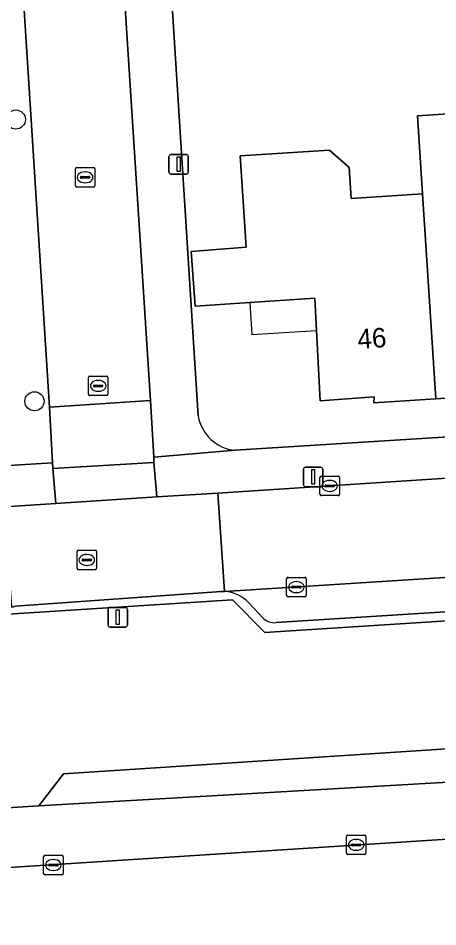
# Model space of a CAD drawing. Extents: x 159626 to 160723, y 388173 to 389416.
# Drawn here: x 160440.24 to 160461.73, y 388327.53 to 388374.02 of the extents above; entities that cross this region are included whole.
import ezdxf

# ---------------------------------------------------------------- set-up
doc = ezdxf.new("R2010")
doc.units = 0
for name, color, linetype in [('IMGEO_Boom', 7, 'Continuous'), ('IMGEO_Erf', 7, 'Continuous'), ('IMGEO_Groenvoorziening', 7, 'Continuous'), ('IMGEO_Kolk', 7, 'Continuous'), ('IMGEO_Lichtmast', 7, 'Continuous'), ('IMGEO_Pand', 7, 'Continuous'), ('IMGEO_Pand_nummerreeks', 7, 'Continuous'), ('IMGEO_Pand_overbouw', 7, 'Continuous'), ('IMGEO_Parkeervlak_open', 7, 'Continuous'), ('IMGEO_Rijbaan_lokaal_open', 7, 'Continuous'), ('IMGEO_Rijbaan_regionaal_gesloten', 7, 'Continuous'), ('IMGEO_Rioolput', 7, 'Continuous'), ('IMGEO_Verkeersbordpaal', 7, 'Continuous'), ('IMGEO_Voetpad_open', 7, 'Continuous')]:
    doc.layers.add(name, color=color, linetype=linetype)

msp = doc.modelspace()

# ---------------------------------------------------------------- linework, layer by layer
at = {"layer": 'IMGEO_Boom'}
for centre in [(160440.123, 388368.835), (160441.073, 388354.42)]:
    msp.add_circle(centre, 0.489, dxfattribs=at)
at = {"layer": 'IMGEO_Erf'}
for points in [[(160505.042, 388420.291), (160500, 388419.981), (160493.644, 388419.591), (160475.279, 388418.463), (160445.47, 388416.632), (160449.463, 388353.672)], [(160464.685, 388354.744), (160461.629, 388354.549), (160458.458, 388354.346), (160458.462, 388354.644), (160455.697, 388354.445), (160455.515, 388358.041), (160455.431, 388359.702), (160452.096, 388359.469), (160449.31, 388359.292), (160449.094, 388362.083), (160451.908, 388362.301), (160451.598, 388366.977), (160456.188, 388367.277), (160457.179, 388366.384), (160457.282, 388364.797), (160460.949, 388365.037), (160460.69, 388369.028), (160469.61, 388369.607)], [(160451.349, 388351.913), (160500, 388354.96), (160500.784, 388355.009), (160506.512, 388355.368)]]:
    msp.add_lwpolyline(points, dxfattribs=at)
msp.add_arc((160451.536, 388354.004), 2.1, 189.1106, 264.8804, dxfattribs=at)
at = {"layer": 'IMGEO_Groenvoorziening'}
for points in [[(160398.695, 388331.202), (160403.057, 388331.467), (160403.067, 388331.305), (160441.302, 388333.713), (160442.552, 388335.356), (160467.15, 388336.963), (160467.275, 388335.225), (160501.835, 388337.484), (160501.213, 388347.873), (160500, 388347.802), (160491.895, 388347.305), (160490.539, 388345.566), (160490.061, 388345.143)], [(160489.377, 388344.926), (160452.877, 388342.587), (160451.214, 388344.256), (160439.719, 388343.519), (160437.971, 388341.554), (160397.13, 388338.982), (160397.594, 388332.119)], [(160501.982, 388335.024), (160501.835, 388337.484), (160467.275, 388335.225), (160441.302, 388333.713), (160403.067, 388331.305), (160403.258, 388328.243), (160416.129, 388329.131), (160431.58, 388330.029), (160482.533, 388333.323), (160501.552, 388334.526)]]:
    msp.add_lwpolyline(points, dxfattribs=at)
msp.add_lwpolyline([(160467.275, 388335.225), (160467.15, 388336.963), (160442.552, 388335.356), (160441.302, 388333.713)], close=True, dxfattribs=at)
at = {"layer": 'IMGEO_Kolk'}
for p, q in [((160443.166, 388365.454), (160443.166, 388366.306)), ((160443.241, 388366.38), (160444.093, 388366.38)), ((160444.167, 388366.306), (160444.167, 388365.454)), ((160443.425, 388365.874), (160443.425, 388365.886)), ((160443.863, 388365.837), (160443.465, 388365.837)), ((160443.468, 388365.923), (160443.866, 388365.923)), ((160443.654, 388366.16), (160443.679, 388366.16)), ((160443.909, 388365.886), (160443.909, 388365.874)), ((160444.093, 388365.38), (160443.241, 388365.38)), ((160443.677, 388365.6), (160443.652, 388365.6)), ((160443.836, 388354.783), (160443.836, 388355.635)), ((160443.911, 388355.709), (160444.763, 388355.709)), ((160444.837, 388355.635), (160444.837, 388354.783)), ((160444.095, 388355.203), (160444.095, 388355.215)), ((160444.533, 388355.166), (160444.135, 388355.166)), ((160444.138, 388355.252), (160444.536, 388355.252)), ((160444.324, 388355.489), (160444.349, 388355.489)), ((160444.579, 388355.215), (160444.579, 388355.203)), ((160444.763, 388354.709), (160443.911, 388354.709)), ((160444.347, 388354.929), (160444.322, 388354.929)), ((160455.692, 388349.665), (160455.692, 388350.517)), ((160455.767, 388350.591), (160456.619, 388350.591)), ((160456.693, 388350.517), (160456.693, 388349.665)), ((160455.951, 388350.085), (160455.951, 388350.097)), ((160456.389, 388350.048), (160455.991, 388350.048)), ((160455.994, 388350.134), (160456.392, 388350.134)), ((160456.18, 388350.371), (160456.205, 388350.371)), ((160456.435, 388350.097), (160456.435, 388350.085)), ((160456.619, 388349.591), (160455.767, 388349.591)), ((160456.203, 388349.811), (160456.178, 388349.811)), ((160454.059, 388345.412), (160454.911, 388345.412)), ((160453.984, 388344.486), (160453.984, 388345.338)), ((160454.243, 388344.906), (160454.243, 388344.918)), ((160454.286, 388344.955), (160454.684, 388344.955)), ((160454.472, 388345.192), (160454.497, 388345.192)), ((160454.727, 388344.918), (160454.727, 388344.906)), ((160454.985, 388345.338), (160454.985, 388344.486)), ((160454.911, 388344.412), (160454.059, 388344.412)), ((160454.681, 388344.869), (160454.283, 388344.869)), ((160454.495, 388344.632), (160454.47, 388344.632)), ((160457.047, 388331.298), (160457.047, 388332.15)), ((160457.122, 388332.224), (160457.974, 388332.224)), ((160457.535, 388332.004), (160457.56, 388332.004)), ((160458.048, 388332.15), (160458.048, 388331.298)), ((160457.306, 388331.718), (160457.306, 388331.73)), ((160457.744, 388331.681), (160457.346, 388331.681)), ((160457.349, 388331.767), (160457.747, 388331.767)), ((160457.558, 388331.444), (160457.533, 388331.444)), ((160457.79, 388331.73), (160457.79, 388331.718)), ((160441.543, 388330.265), (160441.543, 388331.117)), ((160441.618, 388331.191), (160442.47, 388331.191)), ((160442.031, 388330.971), (160442.056, 388330.971)), ((160442.544, 388331.117), (160442.544, 388330.265)), ((160457.974, 388331.224), (160457.122, 388331.224)), ((160441.802, 388330.685), (160441.802, 388330.697)), ((160442.24, 388330.648), (160441.842, 388330.648)), ((160441.845, 388330.734), (160442.243, 388330.734)), ((160442.286, 388330.697), (160442.286, 388330.685)), ((160442.47, 388330.191), (160441.618, 388330.191)), ((160442.054, 388330.411), (160442.029, 388330.411))]:
    msp.add_line(p, q, dxfattribs=at)
for points in [[(160443.166, 388365.454), (160443.166, 388366.306)], [(160443.241, 388366.38), (160444.093, 388366.38)], [(160444.167, 388366.306), (160444.167, 388365.454)], [(160444.093, 388365.38), (160443.241, 388365.38)], [(160443.836, 388354.783), (160443.836, 388355.635)], [(160443.911, 388355.709), (160444.763, 388355.709)], [(160444.837, 388355.635), (160444.837, 388354.783)], [(160444.763, 388354.709), (160443.911, 388354.709)], [(160455.692, 388349.665), (160455.692, 388350.517)], [(160455.767, 388350.591), (160456.619, 388350.591)], [(160456.693, 388350.517), (160456.693, 388349.665)], [(160456.619, 388349.591), (160455.767, 388349.591)], [(160454.059, 388345.412), (160454.911, 388345.412)], [(160453.984, 388344.486), (160453.984, 388345.338)], [(160454.985, 388345.338), (160454.985, 388344.486)], [(160454.911, 388344.412), (160454.059, 388344.412)], [(160457.047, 388331.298), (160457.047, 388332.15)], [(160457.122, 388332.224), (160457.974, 388332.224)], [(160458.048, 388332.15), (160458.048, 388331.298)], [(160441.543, 388330.265), (160441.543, 388331.117)], [(160441.618, 388331.191), (160442.47, 388331.191)], [(160442.544, 388331.117), (160442.544, 388330.265)], [(160457.974, 388331.224), (160457.122, 388331.224)], [(160442.47, 388330.191), (160441.618, 388330.191)]]:
    msp.add_lwpolyline(points, dxfattribs=at)
for centre, radius, start, end in [((160443.243, 388366.304), 0.0765, 91.552, 178.448), ((160443.243, 388366.304), 0.0765, 91.552, 178.448), ((160444.091, 388366.304), 0.0765, 1.552, 88.448), ((160444.091, 388366.304), 0.0765, 1.552, 88.448), ((160443.465, 388365.883), 0.0403, 85.8775, 175.7526), ((160443.462, 388365.873), 0.0366, 178.938, 274.7102), ((160443.866, 388365.88), 0.043, 264.8664, 352.4533), ((160443.87, 388365.885), 0.0386, 1.7309, 96.639), ((160443.243, 388365.456), 0.0765, 181.552, 268.448), ((160443.243, 388365.456), 0.0765, 181.552, 268.448), ((160444.091, 388365.456), 0.0765, 271.552, 358.448), ((160444.091, 388365.456), 0.0765, 271.552, 358.448), ((160443.913, 388355.633), 0.0765, 91.552, 178.448), ((160443.913, 388355.633), 0.0765, 91.552, 178.448), ((160444.761, 388355.633), 0.0765, 1.552, 88.448), ((160444.761, 388355.633), 0.0765, 1.552, 88.448), ((160444.135, 388355.212), 0.0403, 85.8775, 175.7526), ((160444.132, 388355.202), 0.0366, 178.938, 274.7102), ((160444.536, 388355.209), 0.043, 264.8664, 352.4533), ((160444.54, 388355.214), 0.0386, 1.7309, 96.639), ((160443.913, 388354.785), 0.0765, 181.552, 268.448), ((160443.913, 388354.785), 0.0765, 181.552, 268.448), ((160444.761, 388354.785), 0.0765, 271.552, 358.448), ((160444.761, 388354.785), 0.0765, 271.552, 358.448), ((160455.769, 388350.515), 0.0765, 91.552, 178.448), ((160455.769, 388350.515), 0.0765, 91.552, 178.448), ((160456.617, 388350.515), 0.0765, 1.552, 88.448), ((160456.617, 388350.515), 0.0765, 1.552, 88.448), ((160455.991, 388350.094), 0.0403, 85.8775, 175.7526), ((160455.988, 388350.084), 0.0366, 178.938, 274.7102), ((160456.392, 388350.091), 0.043, 264.8664, 352.4533), ((160456.396, 388350.096), 0.0386, 1.7309, 96.639), ((160455.769, 388349.667), 0.0765, 181.552, 268.448), ((160455.769, 388349.667), 0.0765, 181.552, 268.448), ((160456.617, 388349.667), 0.0765, 271.552, 358.448), ((160456.617, 388349.667), 0.0765, 271.552, 358.448), ((160454.061, 388345.336), 0.0765, 91.552, 178.448), ((160454.061, 388345.336), 0.0765, 91.552, 178.448), ((160454.909, 388345.336), 0.0765, 1.552, 88.448), ((160454.909, 388345.336), 0.0765, 1.552, 88.448), ((160454.283, 388344.915), 0.0403, 85.8775, 175.7526), ((160454.28, 388344.905), 0.0366, 178.938, 274.7102), ((160454.684, 388344.912), 0.043, 264.8664, 352.4533), ((160454.688, 388344.917), 0.0386, 1.7309, 96.639), ((160454.061, 388344.488), 0.0765, 181.552, 268.448), ((160454.061, 388344.488), 0.0765, 181.552, 268.448), ((160454.909, 388344.488), 0.0765, 271.552, 358.448), ((160454.909, 388344.488), 0.0765, 271.552, 358.448), ((160457.124, 388332.148), 0.0765, 91.552, 178.448), ((160457.124, 388332.148), 0.0765, 91.552, 178.448), ((160457.972, 388332.148), 0.0765, 1.552, 88.448), ((160457.972, 388332.148), 0.0765, 1.552, 88.448), ((160457.346, 388331.727), 0.0403, 85.8775, 175.7526), ((160457.343, 388331.717), 0.0366, 178.938, 274.7102), ((160457.747, 388331.724), 0.043, 264.8664, 352.4533), ((160457.751, 388331.729), 0.0386, 1.7309, 96.639), ((160441.62, 388331.115), 0.0765, 91.552, 178.448), ((160441.62, 388331.115), 0.0765, 91.552, 178.448), ((160442.468, 388331.115), 0.0765, 1.552, 88.448), ((160442.468, 388331.115), 0.0765, 1.552, 88.448), ((160457.124, 388331.3), 0.0765, 181.552, 268.448), ((160457.124, 388331.3), 0.0765, 181.552, 268.448), ((160457.972, 388331.3), 0.0765, 271.552, 358.448), ((160457.972, 388331.3), 0.0765, 271.552, 358.448), ((160441.842, 388330.694), 0.0403, 85.8775, 175.7526), ((160441.839, 388330.684), 0.0366, 178.938, 274.7102), ((160442.243, 388330.691), 0.043, 264.8664, 352.4533), ((160442.247, 388330.696), 0.0386, 1.7309, 96.639), ((160441.62, 388330.267), 0.0765, 181.552, 268.448), ((160441.62, 388330.267), 0.0765, 181.552, 268.448), ((160442.468, 388330.267), 0.0765, 271.552, 358.448), ((160442.468, 388330.267), 0.0765, 271.552, 358.448)]:
    msp.add_arc(centre, radius, start, end, dxfattribs=at)
for centre, major_axis, ratio, start_param, end_param in [((160443.653, 388365.88), (-0.387, 0.002), 0.722429, 4.712389, 7.853982), ((160443.678, 388365.88), (-0.39, 0.002), 0.717154, 1.570796, 4.712389), ((160444.323, 388355.209), (-0.387, 0.002), 0.722429, 4.712389, 7.853982), ((160444.348, 388355.209), (-0.39, 0.002), 0.717154, 1.570796, 4.712389), ((160456.179, 388350.091), (-0.387, 0.002), 0.722429, 4.712389, 7.853982), ((160456.204, 388350.091), (-0.39, 0.002), 0.717154, 1.570796, 4.712389), ((160454.471, 388344.912), (-0.387, 0.002), 0.722429, 4.712389, 7.853982), ((160454.496, 388344.912), (-0.39, 0.002), 0.717154, 1.570796, 4.712389), ((160457.534, 388331.724), (-0.387, 0.002), 0.722429, 4.712389, 7.853982), ((160457.559, 388331.724), (-0.39, 0.002), 0.717154, 1.570796, 4.712389), ((160442.03, 388330.691), (-0.387, 0.002), 0.722429, 4.712389, 7.853982), ((160442.055, 388330.691), (-0.39, 0.002), 0.717154, 1.570796, 4.712389)]:
    msp.add_ellipse(centre, major_axis=major_axis, ratio=ratio, start_param=start_param, end_param=end_param, dxfattribs=at)
at = {"layer": 'IMGEO_Lichtmast'}
for p, q in [((160447.96, 388366.146), (160447.96, 388366.946)), ((160447.96, 388366.946), (160447.96, 388366.146)), ((160448.06, 388367.046), (160448.85, 388367.046)), ((160448.85, 388367.046), (160448.06, 388367.046)), ((160448.95, 388366.946), (160448.95, 388366.146)), ((160448.95, 388366.146), (160448.95, 388366.946)), ((160448.85, 388366.046), (160448.06, 388366.046)), ((160448.06, 388366.046), (160448.85, 388366.046)), ((160454.848, 388350.147), (160454.848, 388350.947)), ((160454.848, 388350.947), (160454.848, 388350.147)), ((160454.948, 388351.047), (160455.738, 388351.047)), ((160455.738, 388351.047), (160454.948, 388351.047)), ((160455.838, 388350.947), (160455.838, 388350.147)), ((160455.838, 388350.147), (160455.838, 388350.947)), ((160455.738, 388350.047), (160454.948, 388350.047)), ((160454.948, 388350.047), (160455.738, 388350.047))]:
    msp.add_line(p, q, dxfattribs=at)
for points in [[(160448.38, 388366.921), (160448.53, 388366.921), (160448.53, 388366.171), (160448.38, 388366.171), (160448.38, 388366.921)], [(160455.268, 388350.922), (160455.418, 388350.922), (160455.418, 388350.172), (160455.268, 388350.172), (160455.268, 388350.922)]]:
    msp.add_lwpolyline(points, dxfattribs=at)
for centre, start, end in [((160448.06, 388366.946), 90, 180), ((160448.06, 388366.946), 90, 180), ((160448.85, 388366.946), 0, 90), ((160448.85, 388366.946), 360, 90), ((160448.06, 388366.146), 180, 270), ((160448.06, 388366.146), 180, 270), ((160448.85, 388366.146), 270, 0), ((160448.85, 388366.146), 270, 0), ((160454.948, 388350.947), 90, 180), ((160454.948, 388350.947), 90, 180), ((160455.738, 388350.947), 0, 90), ((160455.738, 388350.947), 360, 90), ((160454.948, 388350.147), 180, 270), ((160454.948, 388350.147), 180, 270), ((160455.738, 388350.147), 270, 0), ((160455.738, 388350.147), 270, 0)]:
    msp.add_arc(centre, 0.1, start, end, dxfattribs=at)
at = {"layer": 'IMGEO_Pand'}
for points in [[(160460.949, 388365.037), (160461.629, 388354.549), (160464.685, 388354.744), (160464.666, 388355.043), (160467.424, 388355.218), (160467.198, 388358.811), (160467.096, 388360.434), (160470.192, 388360.63), (160469.704, 388368.16), (160469.61, 388369.607), (160460.69, 388369.028)], [(160460.949, 388365.037), (160457.282, 388364.797), (160457.179, 388366.384), (160456.188, 388367.277), (160451.598, 388366.977), (160451.908, 388362.301), (160449.094, 388362.083), (160449.31, 388359.292), (160452.096, 388359.469), (160455.431, 388359.702), (160455.515, 388358.041), (160455.697, 388354.445), (160458.462, 388354.644), (160458.458, 388354.346), (160461.629, 388354.549)]]:
    msp.add_lwpolyline(points, close=True, dxfattribs=at)
at = {"layer": 'IMGEO_Pand_overbouw'}
msp.add_lwpolyline([(160452.096, 388359.469), (160452.202, 388357.835), (160455.515, 388358.041), (160455.431, 388359.702)], close=True, dxfattribs=at)
at = {"layer": 'IMGEO_Parkeervlak_open'}
for points in [[(160491.895, 388347.305), (160450.804, 388344.681)], [(160453.456, 388343.099), (160489.446, 388345.363)], [(160452.055, 388344.1), (160452.746, 388343.364)]]:
    msp.add_lwpolyline(points, dxfattribs=at)
for centre, radius, start, end in [((160450.728, 388342.88), 1.803, 42.596, 87.581), ((160453.35, 388343.899), 0.807, 221.5391, 277.5258)]:
    msp.add_arc(centre, radius, start, end, dxfattribs=at)
at = {"layer": 'IMGEO_Rijbaan_lokaal_open'}
for points in [[(160443.874, 388403.115), (160438.719, 388402.783), (160441.847, 388354.123), (160447.012, 388354.455)], [(160447.012, 388354.455), (160441.847, 388354.123), (160441.998, 388351.273), (160442.014, 388350.988), (160447.193, 388351.283), (160447.177, 388351.563)], [(160450.468, 388349.725), (160450.804, 388344.681), (160491.895, 388347.305), (160500, 388347.802), (160501.213, 388347.873), (160500.908, 388352.954), (160500, 388352.892), (160492.037, 388352.35), (160485.261, 388351.928), (160474.175, 388351.243), (160467.406, 388350.819)], [(160450.468, 388349.725), (160447.34, 388349.523), (160442.162, 388349.188), (160439.541, 388349.019), (160439.893, 388343.883), (160439.992, 388343.907), (160440.109, 388343.936), (160450.631, 388344.68), (160450.804, 388344.681)]]:
    msp.add_lwpolyline(points, close=True, dxfattribs=at)
at = {"layer": 'IMGEO_Rijbaan_regionaal_gesloten'}
msp.add_lwpolyline([(160498.569, 388330.843), (160501.711, 388331.041), (160501.552, 388334.526), (160482.533, 388333.323), (160431.58, 388330.029), (160416.129, 388329.131), (160403.258, 388328.243), (160402.405, 388328.188), (160398.382, 388327.927), (160391.245, 388327.456), (160384.175, 388326.99), (160373.808, 388325.977), (160353.994, 388323.671), (160342.589, 388322.211), (160341.716, 388322.099)], dxfattribs=at)
at = {"layer": 'IMGEO_Rioolput'}
for p, q in [((160443.328, 388346.802), (160444.18, 388346.802)), ((160443.253, 388345.876), (160443.253, 388346.728)), ((160443.512, 388346.296), (160443.512, 388346.308)), ((160443.555, 388346.345), (160443.953, 388346.345)), ((160443.741, 388346.582), (160443.766, 388346.582)), ((160443.996, 388346.308), (160443.996, 388346.296)), ((160444.254, 388346.728), (160444.254, 388345.876)), ((160443.95, 388346.259), (160443.552, 388346.259)), ((160443.764, 388346.022), (160443.739, 388346.022)), ((160444.18, 388345.802), (160443.328, 388345.802))]:
    msp.add_line(p, q, dxfattribs=at)
for points in [[(160443.328, 388346.802), (160444.18, 388346.802)], [(160443.253, 388345.876), (160443.253, 388346.728)], [(160444.254, 388346.728), (160444.254, 388345.876)], [(160444.18, 388345.802), (160443.328, 388345.802)]]:
    msp.add_lwpolyline(points, dxfattribs=at)
for centre, radius, start, end in [((160443.33, 388346.726), 0.0765, 91.552, 178.448), ((160443.33, 388346.726), 0.0765, 91.552, 178.448), ((160444.178, 388346.726), 0.0765, 1.552, 88.448), ((160444.178, 388346.726), 0.0765, 1.552, 88.448), ((160443.552, 388346.305), 0.0403, 85.8775, 175.7526), ((160443.549, 388346.295), 0.0366, 178.938, 274.7102), ((160443.953, 388346.302), 0.043, 264.8664, 352.4533), ((160443.957, 388346.307), 0.0386, 1.7309, 96.639), ((160443.33, 388345.878), 0.0765, 181.552, 268.448), ((160443.33, 388345.878), 0.0765, 181.552, 268.448), ((160444.178, 388345.878), 0.0765, 271.552, 358.448), ((160444.178, 388345.878), 0.0765, 271.552, 358.448)]:
    msp.add_arc(centre, radius, start, end, dxfattribs=at)
for centre, major_axis, ratio, start_param, end_param in [((160443.74, 388346.302), (-0.387, 0.002), 0.722429, 4.712389, 7.853982), ((160443.765, 388346.302), (-0.39, 0.002), 0.717154, 1.570796, 4.712389)]:
    msp.add_ellipse(centre, major_axis=major_axis, ratio=ratio, start_param=start_param, end_param=end_param, dxfattribs=at)
at = {"layer": 'IMGEO_Verkeersbordpaal'}
for p, q in [((160444.839, 388342.968), (160444.839, 388343.768)), ((160444.839, 388343.768), (160444.839, 388342.968)), ((160444.939, 388343.868), (160445.729, 388343.868)), ((160445.729, 388343.868), (160444.939, 388343.868)), ((160445.829, 388343.768), (160445.829, 388342.968)), ((160445.829, 388342.968), (160445.829, 388343.768)), ((160445.729, 388342.868), (160444.939, 388342.868)), ((160444.939, 388342.868), (160445.729, 388342.868))]:
    msp.add_line(p, q, dxfattribs=at)
msp.add_lwpolyline([(160445.259, 388343.743), (160445.409, 388343.743), (160445.409, 388342.993), (160445.259, 388342.993), (160445.259, 388343.743)], dxfattribs=at)
for centre, start, end in [((160444.939, 388343.768), 90, 180), ((160444.939, 388343.768), 90, 180), ((160445.729, 388343.768), 0, 90), ((160445.729, 388343.768), 360, 90), ((160444.939, 388342.968), 180, 270), ((160444.939, 388342.968), 180, 270), ((160445.729, 388342.968), 270, 0), ((160445.729, 388342.968), 270, 0)]:
    msp.add_arc(centre, 0.1, start, end, dxfattribs=at)
at = {"layer": 'IMGEO_Voetpad_open'}
for points in [[(160445.47, 388416.632), (160445.249, 388419.64), (160444.954, 388424.235), (160442.523, 388424.077), (160443.684, 388406.074), (160443.874, 388403.115), (160447.012, 388354.455), (160447.177, 388351.563), (160451.349, 388351.913)], [(160449.463, 388353.672), (160445.47, 388416.632)], [(160437.814, 388351.02), (160441.998, 388351.273), (160441.847, 388354.123), (160438.719, 388402.783)], [(160442.014, 388350.988), (160441.998, 388351.273), (160437.814, 388351.02), (160389.96, 388347.928), (160349.131, 388345.29), (160347.594, 388345.191), (160272.851, 388340.361), (160268.041, 388339.984)], [(160352.061, 388343.382), (160364.171, 388344.172), (160364.14, 388344.671), (160370.925, 388345.095), (160370.956, 388344.596), (160382.517, 388345.349), (160382.484, 388345.847), (160389.26, 388346.307), (160389.293, 388345.809), (160390.09, 388345.858), (160400.759, 388346.511), (160400.727, 388347.009), (160407.503, 388347.449), (160407.535, 388346.951), (160418.998, 388347.671), (160418.965, 388348.169), (160425.746, 388348.628), (160425.779, 388348.13), (160439.541, 388349.019), (160442.162, 388349.188), (160442.014, 388350.988)], [(160489.446, 388345.363), (160453.456, 388343.099)], [(160278.645, 388331.479), (160390.545, 388338.593), (160393.947, 388338.809), (160397.13, 388338.982), (160437.971, 388341.554), (160439.719, 388343.519), (160451.214, 388344.256), (160452.877, 388342.587), (160489.377, 388344.926)], [(160450.804, 388344.681), (160450.631, 388344.68), (160440.109, 388343.936), (160439.992, 388343.907), (160439.893, 388343.883)], [(160452.746, 388343.364), (160452.055, 388344.1)]]:
    msp.add_lwpolyline(points, dxfattribs=at)
for points in [[(160500.784, 388355.009), (160500, 388354.96), (160451.349, 388351.913), (160447.177, 388351.563), (160447.193, 388351.283), (160447.34, 388349.523), (160450.468, 388349.725), (160467.406, 388350.819), (160467.375, 388351.318), (160474.144, 388351.742), (160474.175, 388351.243), (160485.261, 388351.928), (160485.23, 388352.427), (160492.006, 388352.849), (160492.037, 388352.35), (160500, 388352.892), (160500.908, 388352.954)], [(160447.193, 388351.283), (160442.014, 388350.988), (160442.162, 388349.188), (160447.34, 388349.523)]]:
    msp.add_lwpolyline(points, close=True, dxfattribs=at)
for centre, radius, start, end in [((160451.536, 388354.004), 2.1, 189.1106, 264.8804), ((160450.728, 388342.88), 1.803, 42.596, 87.581), ((160453.35, 388343.899), 0.807, 221.5391, 277.5258)]:
    msp.add_arc(centre, radius, start, end, dxfattribs=at)

# ---------------------------------------------------------------- texts
at = {"layer": 'IMGEO_Pand_nummerreeks'}
msp.add_text('46', height=1, rotation=3.7713, dxfattribs=at).set_placement((160457.638, 388357.098))

doc.saveas('drawing.dxf')
